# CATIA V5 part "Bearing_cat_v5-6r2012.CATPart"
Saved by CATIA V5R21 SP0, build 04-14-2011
Part number: Bearing
Bounding box of the stored display mesh (mm): x -10 to 10, y -17.5 to 17.5, z -17.322 to 17.322
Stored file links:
  D:\APS\CATIA V5-6R-2013-Project\CATIA V5-6R2013_partfiles\Tutorials\c16_catia_v5-6r2013_tut\Cam Follower mechanism\Bearing_cat_v5-6r2012.CATPart
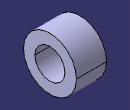
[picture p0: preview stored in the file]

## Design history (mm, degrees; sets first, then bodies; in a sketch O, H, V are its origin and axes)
Body1 (main body)
  Sketch1 on yz-plane, origin (0, 0, 0), H (0, 1, 0), V (0, 0, 1)
    circle A1 centre (0, 0) radius 10
    circle A2 centre (0, 0) radius 17.5
    radius A1 = 10
    radius A2 = 17.5
  Pad1: profile Sketch1, direction (1, 0, 0), length 10, mirrored extent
